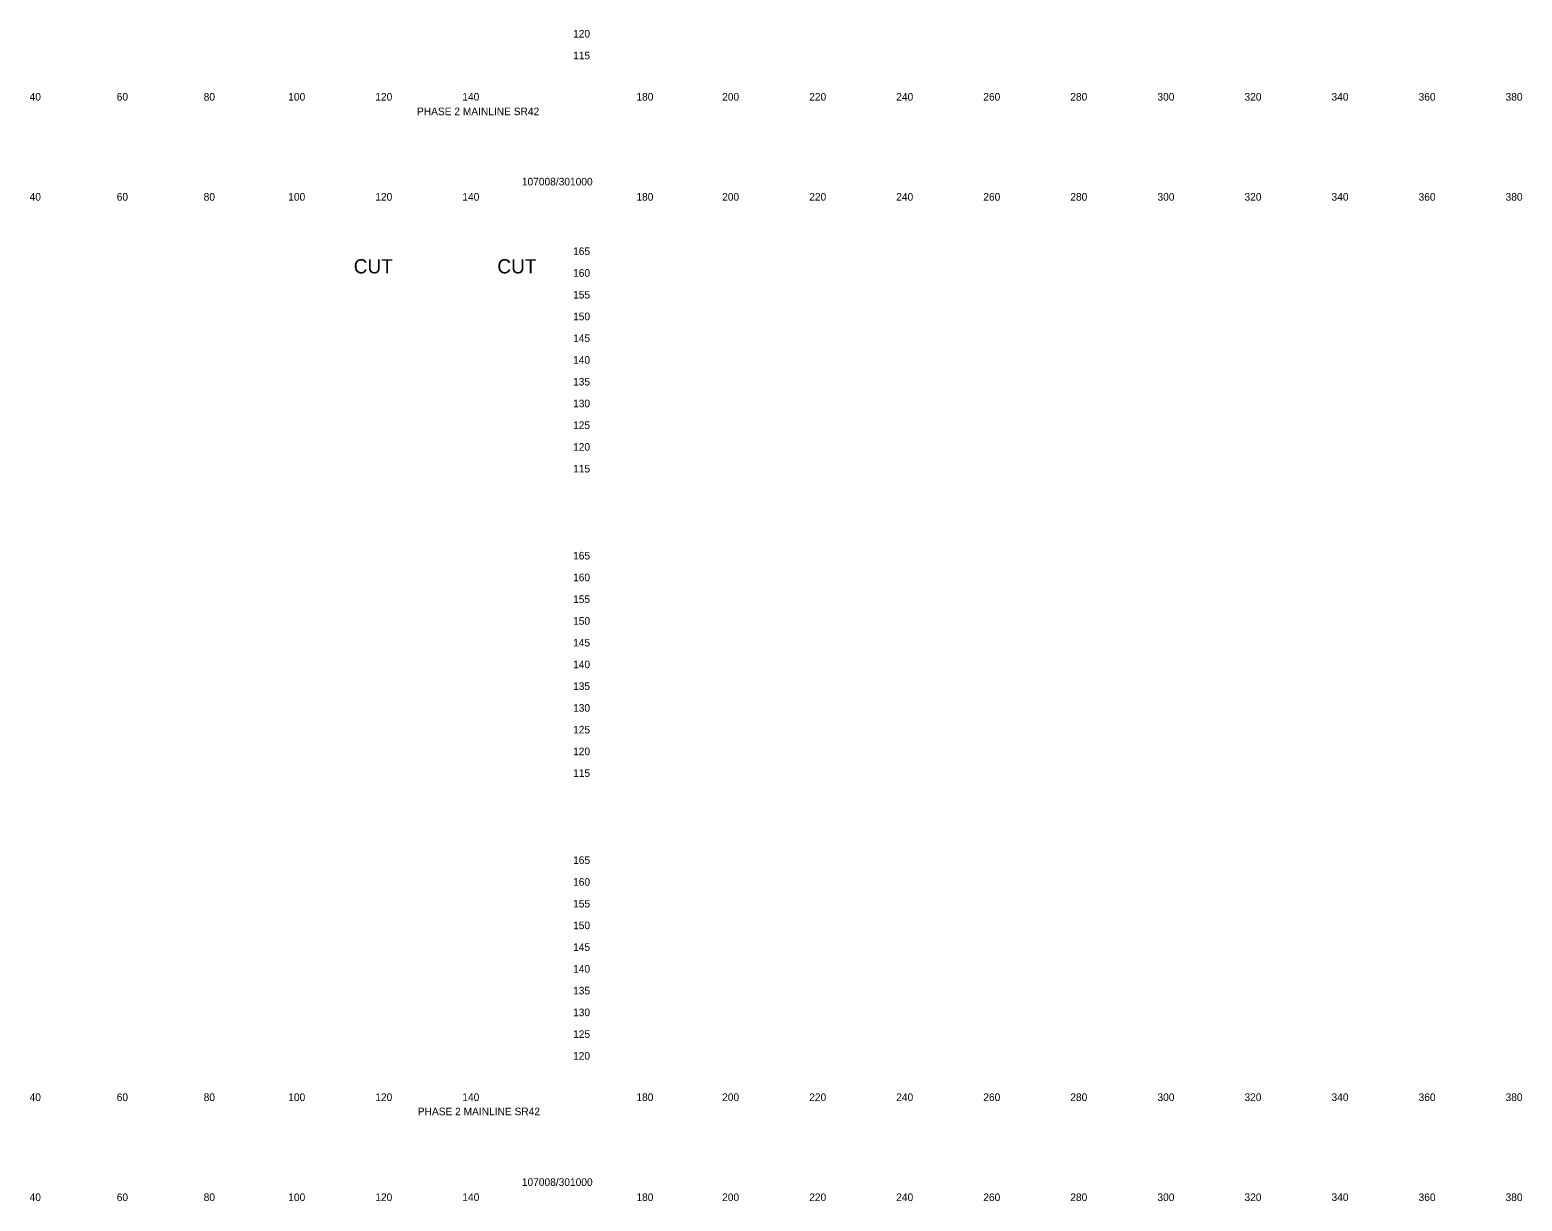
# Model space of a CAD drawing. Extents: x 21281 to 22024, y 6472 to 15208.
# Drawn here: x 21681.3 to 22024.2, y 7832.3 to 8101.6 of the extents above; entities that cross this region are included whole.
import ezdxf

# ---------------------------------------------------------------- set-up
doc = ezdxf.new("R2010")
doc.units = 0
doc.layers.add('XS_SHEET_LABELS_ELEVATION', color=7, linetype='Continuous')
doc.layers.add('XS_SHEET_LABELS_OFFSET', color=7, linetype='Continuous')

msp = doc.modelspace()

# ---------------------------------------------------------------- texts
at = {"layer": 'XS_SHEET_LABELS_ELEVATION'}
for s, p in [('  120  ', (21804.84, 8099.84)), ('  115  ', (21804.84, 8094.84)), ('  165  ', (21804.84, 8049.84)), ('  160  ', (21804.84, 8044.84)), ('  155  ', (21804.84, 8039.84)), ('  150  ', (21804.84, 8034.84)), ('  145  ', (21804.84, 8029.84)), ('  140  ', (21804.84, 8024.84)), ('  135  ', (21804.84, 8019.84)), ('  130  ', (21804.84, 8014.84)), ('  125  ', (21804.84, 8009.84)), ('  120  ', (21804.84, 8004.84)), ('  115  ', (21804.84, 7999.84)), ('  165  ', (21804.84, 7979.84)), ('  160  ', (21804.84, 7974.84)), ('  155  ', (21804.84, 7969.84)), ('  150  ', (21804.84, 7964.84)), ('  145  ', (21804.84, 7959.84)), ('  140  ', (21804.84, 7954.84)), ('  135  ', (21804.84, 7949.84)), ('  130  ', (21804.84, 7944.84)), ('  125  ', (21804.84, 7939.84)), ('  120  ', (21804.84, 7934.84)), ('  115  ', (21804.84, 7929.84)), ('  165  ', (21804.84, 7909.84)), ('  160  ', (21804.84, 7904.84)), ('  155  ', (21804.84, 7899.84)), ('  150  ', (21804.84, 7894.84)), ('  145  ', (21804.84, 7889.84)), ('  140  ', (21804.84, 7884.84)), ('  135  ', (21804.84, 7879.84)), ('  130  ', (21804.84, 7874.84)), ('  125  ', (21804.84, 7869.84)), ('  120  ', (21804.84, 7864.84))]:
    msp.add_text(s, height=1.75, dxfattribs=at).set_placement(p)
at = {"layer": 'XS_SHEET_LABELS_OFFSET'}
for s, height, p in [('  40  ', 1.75, (21679.95, 8085.34)), ('  60  ', 1.75, (21699.97, 8085.34)), ('  80  ', 1.75, (21719.95, 8085.34)), ('  100  ', 1.75, (21739.39, 8085.34)), ('  120  ', 1.75, (21759.39, 8085.34)), ('  140  ', 1.75, (21779.39, 8085.34)), ('  180  ', 1.75, (21819.39, 8085.34)), ('  200  ', 1.75, (21839.1, 8085.34)), ('  220  ', 1.75, (21859.1, 8085.34)), ('  240  ', 1.75, (21879.1, 8085.34)), ('  260  ', 1.75, (21899.11, 8085.34)), ('  280  ', 1.75, (21919.1, 8085.34)), ('  300  ', 1.75, (21939.13, 8085.34)), ('  320  ', 1.75, (21959.13, 8085.34)), ('  340  ', 1.75, (21979.13, 8085.34)), ('  360  ', 1.75, (21999.14, 8085.34)), ('  380  ', 1.75, (22019.13, 8085.34)), ('PHASE 2 MAINLINE SR42', 1.75, (21770.27, 8081.98)), ('107008/301000', 1.75, (21794.37, 8065.84)), ('  40  ', 1.75, (21679.95, 8062.34)), ('  60  ', 1.75, (21699.97, 8062.34)), ('  80  ', 1.75, (21719.95, 8062.34)), ('  100  ', 1.75, (21739.39, 8062.34)), ('  120  ', 1.75, (21759.39, 8062.34)), ('  140  ', 1.75, (21779.39, 8062.34)), ('  180  ', 1.75, (21819.39, 8062.34)), ('  200  ', 1.75, (21839.1, 8062.34)), ('  220  ', 1.75, (21859.1, 8062.34)), ('  240  ', 1.75, (21879.1, 8062.34)), ('  260  ', 1.75, (21899.11, 8062.34)), ('  280  ', 1.75, (21919.1, 8062.34)), ('  300  ', 1.75, (21939.13, 8062.34)), ('  320  ', 1.75, (21959.13, 8062.34)), ('  340  ', 1.75, (21979.13, 8062.34)), ('  360  ', 1.75, (21999.14, 8062.34)), ('  380  ', 1.75, (22019.13, 8062.34)), ('CUT', 3.273, (21755.74, 8045.61)), ('CUT', 3.273, (21788.74, 8045.61)), ('  40  ', 1.75, (21679.95, 7855.34)), ('  60  ', 1.75, (21699.97, 7855.34)), ('  80  ', 1.75, (21719.95, 7855.34)), ('  100  ', 1.75, (21739.39, 7855.34)), ('  120  ', 1.75, (21759.39, 7855.34)), ('  140  ', 1.75, (21779.39, 7855.34)), ('  180  ', 1.75, (21819.39, 7855.34)), ('  200  ', 1.75, (21839.1, 7855.34)), ('  220  ', 1.75, (21859.1, 7855.34)), ('  240  ', 1.75, (21879.1, 7855.34)), ('  260  ', 1.75, (21899.11, 7855.34)), ('  280  ', 1.75, (21919.1, 7855.34)), ('  300  ', 1.75, (21939.13, 7855.34)), ('  320  ', 1.75, (21959.13, 7855.34)), ('  340  ', 1.75, (21979.13, 7855.34)), ('  360  ', 1.75, (21999.14, 7855.34)), ('  380  ', 1.75, (22019.13, 7855.34)), ('PHASE 2 MAINLINE SR42', 1.75, (21770.45, 7852.06)), ('107008/301000', 1.75, (21794.37, 7835.82)), ('  40  ', 1.75, (21679.95, 7832.34)), ('  60  ', 1.75, (21699.97, 7832.34)), ('  80  ', 1.75, (21719.95, 7832.34)), ('  100  ', 1.75, (21739.39, 7832.34)), ('  120  ', 1.75, (21759.39, 7832.34)), ('  140  ', 1.75, (21779.39, 7832.34)), ('  180  ', 1.75, (21819.39, 7832.34)), ('  200  ', 1.75, (21839.1, 7832.34)), ('  220  ', 1.75, (21859.1, 7832.34)), ('  240  ', 1.75, (21879.1, 7832.34)), ('  260  ', 1.75, (21899.11, 7832.34)), ('  280  ', 1.75, (21919.1, 7832.34)), ('  300  ', 1.75, (21939.13, 7832.34)), ('  320  ', 1.75, (21959.13, 7832.34)), ('  340  ', 1.75, (21979.13, 7832.34)), ('  360  ', 1.75, (21999.14, 7832.34)), ('  380  ', 1.75, (22019.13, 7832.34))]:
    msp.add_text(s, height=height, dxfattribs=at).set_placement(p)

doc.saveas('drawing.dxf')
